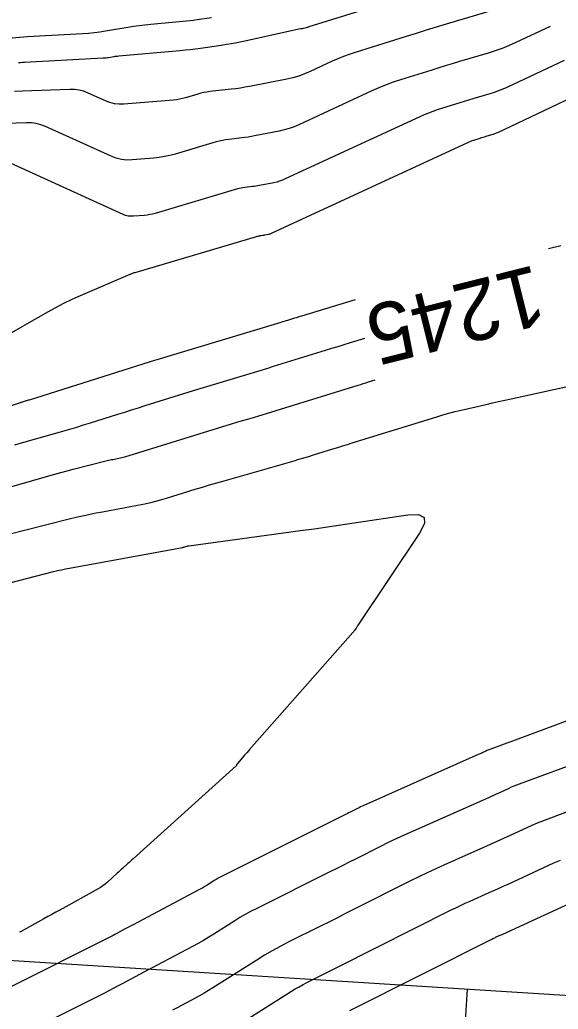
# Model space of a CAD drawing. Extents: x 658976 to 668726, y 639543 to 647196.
# Drawn here: x 662390.8 to 662444.6, y 642050 to 642148.9 of the extents above; entities that cross this region are included whole.
import ezdxf

# ---------------------------------------------------------------- set-up
doc = ezdxf.new("R2010")
doc.units = 0
for name, color, linetype in [('Ex_Contour Labels', 7, 'Continuous'), ('Ex_Major Contours', 7, 'Continuous'), ('Ex_Minor Contours', 7, 'Continuous'), ('R_Grid', 7, 'Continuous'), ('R_Water', 7, 'Continuous')]:
    doc.layers.add(name, color=color, linetype=linetype)

msp = doc.modelspace()

# ---------------------------------------------------------------- linework, layer by layer
at = {"layer": 'Ex_Major Contours'}
for points in [[(662445.176, 642144.863), (662439.46, 642142.168), (662439.049, 642141.984), (662438.633, 642141.816), (662438.21, 642141.663), (662437.781, 642141.527), (662436.053, 642141.014), (662435.621, 642140.885), (662435.19, 642140.755), (662434.759, 642140.622), (662434.329, 642140.489), (662432.511, 642139.919), (662432.068, 642139.772), (662431.63, 642139.611), (662431.197, 642139.435), (662430.77, 642139.246), (662417.319, 642133.018), (662417.042, 642132.9), (662416.76, 642132.799), (662416.471, 642132.714), (662416.178, 642132.647), (662414.767, 642132.369), (662414.582, 642132.334), (662414.397, 642132.304), (662414.212, 642132.277), (662414.026, 642132.254), (662413.28, 642132.171), (662413.094, 642132.147), (662412.91, 642132.114), (662412.728, 642132.072), (662412.547, 642132.023), (662404.324, 642129.584), (662404.061, 642129.513), (662403.794, 642129.456), (662403.526, 642129.413), (662403.254, 642129.383), (662402.164, 642129.293), (662401.894, 642129.287), (662401.63, 642129.316), (662401.372, 642129.378), (662401.12, 642129.474), (662388.295, 642135.289)], [(662390.317, 642106.444), (662391.198, 642106.701), (662395.114, 642107.82), (662395.803, 642108.019), (662396.491, 642108.223), (662397.177, 642108.432), (662397.862, 642108.646), (662400.598, 642109.509), (662401.282, 642109.725), (662401.967, 642109.939), (662402.652, 642110.153), (662403.337, 642110.366), (662408.153, 642111.86), (662408.819, 642112.066), (662409.485, 642112.27), (662410.151, 642112.473), (662410.818, 642112.675), (662413.487, 642113.478), (662414.154, 642113.679), (662414.821, 642113.882), (662415.487, 642114.087), (662416.153, 642114.292), (662421.333, 642115.899), (662421.964, 642116.094), (662422.595, 642116.288), (662423.227, 642116.481), (662423.859, 642116.672), (662425.261, 642117.094)], [(662446.287, 642070.056), (662443.545, 642069.038), (662443.019, 642068.837), (662442.496, 642068.625), (662441.978, 642068.404), (662441.464, 642068.173), (662439.416, 642067.228), (662438.904, 642066.993), (662438.39, 642066.759), (662437.876, 642066.528), (662437.361, 642066.298), (662433.227, 642064.462), (662432.369, 642064.074), (662431.516, 642063.676), (662430.667, 642063.268), (662429.823, 642062.85), (662424.088, 642059.962), (662423.281, 642059.555), (662422.473, 642059.149), (662421.665, 642058.744), (662420.856, 642058.339), (662417.623, 642056.721), (662416.82, 642056.307), (662416.028, 642055.872), (662415.248, 642055.418), (662414.479, 642054.944), (662410.085, 642052.157), (662409.652, 642051.888), (662409.214, 642051.628), (662408.771, 642051.377), (662408.322, 642051.135), (662406.518, 642050.183), (662406.067, 642049.945)]]:
    msp.add_lwpolyline(points, dxfattribs=at)
at = {"layer": 'Ex_Minor Contours'}
for points in [[(662429.276, 642151.227), (662419.674, 642148.211), (662419.607, 642148.191), (662419.54, 642148.172), (662419.473, 642148.154), (662419.405, 642148.137), (662419.135, 642148.072), (662419.067, 642148.056), (662418.999, 642148.041), (662418.931, 642148.025), (662418.863, 642148.011), (662412.981, 642146.74), (662412.47, 642146.635), (662411.958, 642146.538), (662411.444, 642146.45), (662410.928, 642146.37), (662408.863, 642146.071), (662408.346, 642145.999), (662407.828, 642145.935), (662407.31, 642145.879), (662406.79, 642145.829), (662400.702, 642145.29), (662400.571, 642145.277), (662400.441, 642145.262), (662400.311, 642145.244), (662400.181, 642145.223), (662399.662, 642145.135), (662399.532, 642145.115), (662399.402, 642145.099), (662399.272, 642145.086), (662399.14, 642145.078), (662391.284, 642144.665), (662391.078, 642144.654), (662390.871, 642144.641), (662390.665, 642144.626)], [(662438.226, 642149.914), (662433.389, 642148.479), (662432.391, 642148.18), (662431.394, 642147.878), (662430.398, 642147.572), (662429.403, 642147.262), (662424.304, 642145.664), (662423.723, 642145.472), (662423.149, 642145.261), (662422.583, 642145.031), (662422.024, 642144.783), (662419.801, 642143.754), (662419.239, 642143.514), (662418.667, 642143.309), (662418.083, 642143.138), (662417.488, 642143.002), (662413.755, 642142.265), (662413.301, 642142.181), (662412.845, 642142.106), (662412.388, 642142.04), (662411.93, 642141.984), (662409.799, 642141.747), (662409.488, 642141.705), (662409.181, 642141.65), (662408.876, 642141.581), (662408.573, 642141.499), (662407.37, 642141.142), (662407.067, 642141.061), (662406.762, 642140.995), (662406.454, 642140.945), (662406.142, 642140.912), (662401.194, 642140.503), (662400.722, 642140.493), (662400.259, 642140.542), (662399.807, 642140.651), (662399.365, 642140.82), (662397.618, 642141.612), (662397.176, 642141.783), (662396.723, 642141.899), (662396.26, 642141.962), (662395.786, 642141.97), (662391.072, 642141.785), (662390.255, 642141.748)], [(662409.942, 642149.119), (662408.523, 642148.914), (662408.168, 642148.865), (662407.812, 642148.821), (662407.456, 642148.782), (662407.099, 642148.748), (662403.877, 642148.462), (662403.307, 642148.406), (662402.74, 642148.339), (662402.174, 642148.26), (662401.609, 642148.171), (662399.353, 642147.788), (662398.789, 642147.701), (662398.222, 642147.63), (662397.653, 642147.575), (662397.083, 642147.537), (662393.985, 642147.375), (662393.38, 642147.341), (662392.776, 642147.303), (662392.171, 642147.26), (662391.568, 642147.214), (662388.887, 642146.997)], [(662443.782, 642148.269), (662440.363, 642146.657), (662439.683, 642146.352), (662438.993, 642146.073), (662438.293, 642145.821), (662437.583, 642145.596), (662434.721, 642144.746), (662434.006, 642144.533), (662433.292, 642144.316), (662432.579, 642144.097), (662431.866, 642143.875), (662428.855, 642142.932), (662428.121, 642142.688), (662427.395, 642142.422), (662426.679, 642142.131), (662425.971, 642141.818), (662418.68, 642138.442), (662418.2, 642138.237), (662417.711, 642138.061), (662417.212, 642137.915), (662416.703, 642137.799), (662414.261, 642137.317), (662413.942, 642137.257), (662413.621, 642137.205), (662413.3, 642137.159), (662412.978, 642137.119), (662411.686, 642136.976), (662411.365, 642136.933), (662411.047, 642136.875), (662410.731, 642136.804), (662410.418, 642136.719), (662406.331, 642135.507), (662405.805, 642135.365), (662405.273, 642135.251), (662404.737, 642135.165), (662404.195, 642135.106), (662402.017, 642134.926), (662401.479, 642134.915), (662400.952, 642134.971), (662400.437, 642135.095), (662399.933, 642135.287), (662393.352, 642138.271), (662392.898, 642138.447), (662392.432, 642138.567), (662391.956, 642138.631), (662391.468, 642138.639), (662389.394, 642138.558)], [(662388.812, 642116.999), (662393.596, 642119.735), (662394.396, 642120.178), (662395.209, 642120.597), (662396.033, 642120.993), (662396.869, 642121.366), (662401.835, 642123.497), (662401.876, 642123.515), (662401.918, 642123.534), (662401.96, 642123.553), (662402.001, 642123.572), (662402.235, 642123.68), (662402.243, 642123.682), (662402.25, 642123.683), (662402.257, 642123.682), (662402.264, 642123.68), (662402.306, 642123.661), (662402.31, 642123.66), (662402.317, 642123.661), (662414.676, 642127.327), (662414.724, 642127.341), (662414.773, 642127.352), (662414.823, 642127.361), (662414.873, 642127.367), (662415.073, 642127.39), (662415.123, 642127.396), (662415.173, 642127.403), (662415.223, 642127.411), (662415.273, 642127.42), (662415.652, 642127.495), (662415.731, 642127.513), (662415.808, 642127.536), (662415.884, 642127.563), (662415.959, 642127.595), (662435.569, 642136.674), (662435.716, 642136.739), (662435.864, 642136.8), (662436.015, 642136.855), (662436.167, 642136.906), (662436.792, 642137.102), (662436.94, 642137.148), (662437.088, 642137.193), (662437.237, 642137.238), (662437.385, 642137.282), (662437.979, 642137.459), (662438.127, 642137.506), (662438.272, 642137.558), (662438.415, 642137.616), (662438.557, 642137.679), (662446.569, 642141.457)], [(662444.845, 642126.352), (662443.635, 642126.049)], [(662424.301, 642120.925), (662418.946, 642119.312), (662418.773, 642119.259), (662418.599, 642119.206), (662418.426, 642119.153), (662418.253, 642119.1), (662417.56, 642118.885), (662417.386, 642118.831), (662417.213, 642118.778), (662417.039, 642118.725), (662416.866, 642118.673), (662405.167, 642115.152), (662405.055, 642115.118), (662404.943, 642115.084), (662404.831, 642115.05), (662404.719, 642115.015), (662404.272, 642114.876), (662404.161, 642114.842), (662404.049, 642114.807), (662403.937, 642114.772), (662403.826, 642114.737), (662391.723, 642110.917), (662391.65, 642110.894), (662391.577, 642110.872), (662391.504, 642110.85), (662391.43, 642110.829), (662391.136, 642110.745), (662391.062, 642110.724), (662390.989, 642110.701), (662390.916, 642110.679), (662390.843, 642110.655), (662373.673, 642105.017)], [(662376.807, 642094.243), (662395.747, 642099.042), (662396.568, 642099.243), (662397.391, 642099.429), (662398.218, 642099.603), (662399.048, 642099.762), (662402.56, 642100.406), (662403.295, 642100.552), (662404.025, 642100.72), (662404.749, 642100.909), (662405.468, 642101.119), (662408.334, 642102.005), (662409.051, 642102.225), (662409.77, 642102.44), (662410.489, 642102.652), (662411.21, 642102.86), (662418.208, 642104.861), (662418.695, 642105.001), (662419.181, 642105.145), (662419.667, 642105.29), (662420.151, 642105.439), (662422.088, 642106.037), (662422.573, 642106.187), (662423.057, 642106.336), (662423.541, 642106.486), (662424.025, 642106.637), (662432.46, 642109.256), (662433.07, 642109.438), (662433.682, 642109.61), (662434.298, 642109.77), (662434.916, 642109.918), (662437.398, 642110.488), (662438.018, 642110.63), (662438.639, 642110.77), (662439.26, 642110.909), (662439.881, 642111.046), (662452.794, 642113.888)], [(662388.456, 642101.854), (662393.699, 642103.353), (662394.306, 642103.524), (662394.915, 642103.691), (662395.525, 642103.853), (662396.137, 642104.01), (662399.516, 642104.866), (662399.663, 642104.902), (662399.811, 642104.936), (662399.959, 642104.967), (662400.107, 642104.995), (662400.702, 642105.104), (662400.85, 642105.134), (662400.998, 642105.168), (662401.144, 642105.206), (662401.289, 642105.248), (662411.942, 642108.54), (662412.161, 642108.607), (662412.38, 642108.673), (662412.6, 642108.738), (662412.82, 642108.801), (662413.7, 642109.053), (662413.92, 642109.117), (662414.14, 642109.181), (662414.359, 642109.247), (662414.578, 642109.314), (662424.606, 642112.411), (662424.864, 642112.491), (662425.123, 642112.571), (662425.382, 642112.651), (662425.64, 642112.732), (662426.303, 642112.937)], [(662387.961, 642092.2), (662394.157, 642093.77), (662394.56, 642093.868), (662394.964, 642093.96), (662395.37, 642094.045), (662395.777, 642094.123), (662407.049, 642096.19), (662407.06, 642096.192), (662407.07, 642096.195), (662407.081, 642096.198), (662407.092, 642096.201), (662407.134, 642096.214), (662407.155, 642096.22), (662407.176, 642096.227), (662407.48, 642096.313), (662407.535, 642096.328), (662407.59, 642096.34), (662407.645, 642096.351), (662407.701, 642096.36), (662418.857, 642097.875), (662420.198, 642098.06), (662421.538, 642098.25), (662422.877, 642098.444), (662424.216, 642098.644), (662429.568, 642099.454), (662430.645, 642099.491), (662431.2, 642099.196), (662431.231, 642098.568), (662430.741, 642097.609), (662424.545, 642088.339), (662424.508, 642088.284), (662424.472, 642088.229), (662424.435, 642088.175), (662424.398, 642088.12), (662424.251, 642087.902), (662424.214, 642087.848), (662424.174, 642087.795), (662424.133, 642087.744), (662424.091, 642087.694), (662413.764, 642075.987), (662413.64, 642075.846), (662413.515, 642075.705), (662413.392, 642075.564), (662413.268, 642075.422), (662412.556, 642074.608), (662412.542, 642074.59), (662412.529, 642074.571), (662412.517, 642074.551), (662412.507, 642074.53), (662412.469, 642074.446), (662412.459, 642074.425), (662412.446, 642074.406), (662412.432, 642074.388), (662412.416, 642074.372), (662402.115, 642065.073), (662401.983, 642064.953), (662401.851, 642064.833), (662401.72, 642064.713), (662401.589, 642064.592), (662401.066, 642064.109), (662400.935, 642063.988), (662400.804, 642063.867), (662400.673, 642063.747), (662400.542, 642063.626), (662399.547, 642062.715), (662399.332, 642062.53), (662399.107, 642062.359), (662398.873, 642062.201), (662398.629, 642062.057), (662394.786, 642059.942), (662394.389, 642059.724), (662393.991, 642059.505), (662393.594, 642059.286), (662393.197, 642059.068), (662390.855, 642057.781), (662390.833, 642057.769), (662390.812, 642057.757), (662390.79, 642057.746)], [(662447.2, 642079.495), (662440.304, 642076.936), (662440.03, 642076.834), (662439.755, 642076.733), (662439.48, 642076.632), (662439.205, 642076.532), (662437.75, 642076.004), (662437.652, 642075.967), (662437.555, 642075.927), (662437.46, 642075.885), (662437.365, 642075.839), (662436.989, 642075.654), (662436.895, 642075.608), (662436.801, 642075.563), (662436.706, 642075.519), (662436.61, 642075.476), (662425.161, 642070.39), (662425.007, 642070.321), (662424.855, 642070.25), (662424.703, 642070.177), (662424.553, 642070.102), (662423.952, 642069.8), (662423.801, 642069.724), (662423.651, 642069.648), (662423.501, 642069.573), (662423.35, 642069.498), (662411.021, 642063.329), (662410.821, 642063.225), (662410.623, 642063.117), (662410.428, 642063.003), (662410.236, 642062.885), (662409.474, 642062.402), (662409.282, 642062.283), (662409.089, 642062.168), (662408.892, 642062.056), (662408.694, 642061.949), (662402.053, 642058.446), (662401.859, 642058.343), (662401.665, 642058.24), (662401.471, 642058.136), (662401.278, 642058.032), (662400.505, 642057.616), (662400.311, 642057.513), (662400.117, 642057.411), (662399.922, 642057.31), (662399.726, 642057.211), (662389.757, 642052.203)], [(662446.743, 642074.775), (662440.685, 642072.527), (662440.426, 642072.428), (662440.168, 642072.323), (662439.912, 642072.214), (662439.659, 642072.1), (662438.648, 642071.634), (662438.395, 642071.518), (662438.142, 642071.403), (662437.888, 642071.288), (662437.634, 642071.175), (662429.489, 642067.557), (662428.836, 642067.262), (662428.187, 642066.96), (662427.542, 642066.649), (662426.9, 642066.331), (662424.342, 642065.043), (662423.702, 642064.721), (662423.062, 642064.399), (662422.422, 642064.078), (662421.781, 642063.757), (662414.411, 642060.07), (662413.865, 642059.788), (662413.327, 642059.492), (662412.796, 642059.183), (662412.273, 642058.861), (662410.197, 642057.544), (662409.675, 642057.22), (662409.146, 642056.906), (662408.612, 642056.604), (662408.071, 642056.311), (662404.519, 642054.437), (662404.08, 642054.205), (662403.641, 642053.972), (662403.203, 642053.738), (662402.766, 642053.503), (662401.016, 642052.561), (662400.578, 642052.327), (662400.138, 642052.096), (662399.696, 642051.868), (662399.253, 642051.644), (662393.344, 642048.675)], [(662409.695, 642046.593), (662417.948, 642051.828), (662418.327, 642052.062), (662418.711, 642052.285), (662419.101, 642052.499), (662419.496, 642052.703), (662421.088, 642053.5), (662421.486, 642053.699), (662421.884, 642053.899), (662422.282, 642054.099), (662422.679, 642054.299), (662433.901, 642059.95), (662434.368, 642060.181), (662434.837, 642060.407), (662435.31, 642060.627), (662435.784, 642060.842), (662437.689, 642061.688), (662438.165, 642061.9), (662438.64, 642062.114), (662439.114, 642062.33), (662439.588, 642062.547), (662444.15, 642064.652), (662444.483, 642064.802), (662444.818, 642064.945)], [(662423.783, 642049.901), (662437.979, 642057.05), (662438.069, 642057.095), (662438.159, 642057.138), (662438.25, 642057.18), (662438.341, 642057.222), (662438.708, 642057.384), (662438.799, 642057.425), (662438.89, 642057.466), (662438.982, 642057.508), (662439.073, 642057.549), (662447.014, 642061.214)]]:
    msp.add_lwpolyline(points, dxfattribs=at)
at = {"layer": 'R_Grid'}
for p, q in [((661637.1, 642102.197), (663134.15, 642008.176)), ((662419.857, 641802.544), (662435.527, 642052.052))]:
    msp.add_line(p, q, dxfattribs=at)
at = {"layer": 'R_Water'}
for centre, radius, start, end in [((662480.693, 642054.641), 160.334, 105.24685, 156.81084), ((662471.551, 642047.67), 150, 101.54523, 153.10921), ((662462.41, 642040.7), 140.382, 97.31659, 148.88058)]:
    msp.add_arc(centre, radius, start, end, dxfattribs=at)

# ---------------------------------------------------------------- texts
at = {"layer": 'Ex_Contour Labels'}
msp.add_text('1245', height=6, rotation=194.06783, dxfattribs=at).set_placement((662442.315, 642124.46))

doc.saveas('drawing.dxf')
